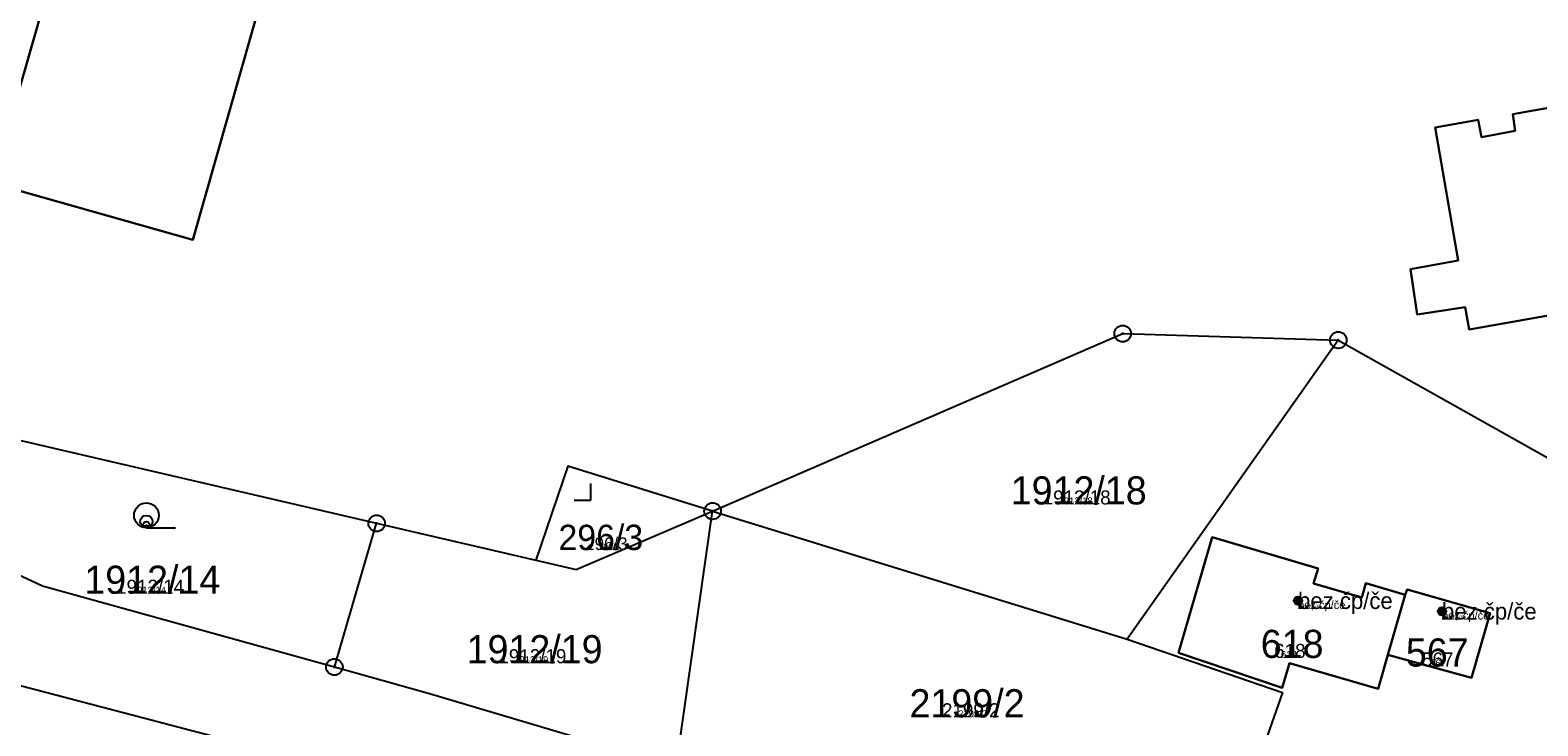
# Model space of a CAD drawing. Extents: x -744652 to -739090, y -980828 to -975855.
# Drawn here: x -742346.1 to -742254.9, y -978565.5 to -978523.4 of the extents above; entities that cross this region are included whole.
import ezdxf

# ---------------------------------------------------------------- set-up
doc = ezdxf.new("R2010")
doc.units = 0
for name, color, linetype in [('KAT_02_hranice parcel', 7, 'Continuous'), ('KAT_03_1000_st čísla parcelní', 7, 'Continuous'), ('KAT_03_1000_čísla parcelní', 7, 'Continuous'), ('KAT_03_1000_čísla popisná', 7, 'Continuous'), ('KAT_03_100_st čísla parcelní', 7, 'Continuous'), ('KAT_03_100_čísla parcelní', 7, 'Continuous'), ('KAT_03_100_čísla popisná', 7, 'Continuous'), ('KAT_03_250_st čísla parcelní', 7, 'Continuous'), ('KAT_03_250_čísla parcelní', 7, 'Continuous'), ('KAT_03_250_čísla popisná', 7, 'Continuous'), ('KAT_03_500_st čísla parcelní', 7, 'Continuous'), ('KAT_03_500_čísla parcelní', 7, 'Continuous'), ('KAT_03_500_čísla popisná', 7, 'Continuous'), ('KAT_05_1000_značky kultur', 7, 'Continuous'), ('KAT_05_100_značky kultur', 7, 'Continuous'), ('KAT_05_250_značky kultur', 7, 'Continuous'), ('KAT_05_500_značky kultur', 7, 'Continuous'), ('KAT_07_1000_značky budov', 7, 'Continuous'), ('KAT_07_100_značky budov', 7, 'Continuous'), ('KAT_07_500_značky budov', 7, 'Continuous'), ('KAT_11_značky bodu BP', 7, 'Continuous'), ('KAT_14_plocha_budovy', 7, 'Continuous')]:
    doc.layers.add(name, color=color, linetype=linetype)

msp = doc.modelspace()

# ---------------------------------------------------------------- linework, layer by layer
at = {"layer": 'KAT_02_hranice parcel'}
for p, q in [((-742266.98, -978542.14), (-742279.73, -978560.22)), ((-742266.98, -978542.14), (-742239.25, -978557.74)), ((-742327.66, -978561.91), (-742325.11, -978553.22)), ((-742325.11, -978553.22), (-742315.48, -978555.45)), ((-742313.05, -978556.01), (-742304.8, -978552.48)), ((-742307, -978567.97), (-742304.8, -978552.48)), ((-742304.8, -978552.48), (-742279.73, -978560.22)), ((-742315.48, -978555.45), (-742313.05, -978556.01)), ((-742262.93, -978557.54), (-742263.98, -978561.18)), ((-742355.44, -978560.72), (-742332.68, -978566.69))]:
    msp.add_line(p, q, dxfattribs=at)
for points in [[(-742321.29, -978483.58), (-742336.22, -978536.07), (-742348.35, -978532.65), (-742333.05, -978479.2)], [(-742256.28, -978529.49), (-742256.42, -978528.48), (-742243.47, -978526.19), (-742243.22, -978527.52), (-742239.22, -978526.8), (-742238.57, -978530.55), (-742238.97, -978530.61), (-742238.72, -978532.25), (-742238.13, -978532.17), (-742237.29, -978537.66), (-742259.07, -978541.51), (-742259.31, -978540.16), (-742262.2, -978540.59), (-742262.61, -978537.85), (-742259.74, -978537.33), (-742261.13, -978529.29), (-742258.52, -978528.83), (-742258.33, -978529.88), (-742256.28, -978529.49)], [(-742304.8, -978552.48), (-742280.01, -978541.75), (-742266.98, -978542.14)], [(-742352.77, -978553.55), (-742351.57, -978547.06), (-742325.11, -978553.22)], [(-742304.8, -978552.48), (-742313.56, -978549.77), (-742315.48, -978555.45)], [(-742327.66, -978561.91), (-742345.31, -978557.03), (-742352.77, -978553.55)], [(-742263.98, -978561.18), (-742264.57, -978563.23), (-742269.93, -978561.68), (-742270.38, -978563.16), (-742276.63, -978561.05), (-742274.6, -978554.05), (-742268.2, -978555.96), (-742268.48, -978556.86), (-742265.55, -978557.7), (-742265.31, -978556.83), (-742262.93, -978557.54)], [(-742262.93, -978557.54), (-742262.82, -978557.23), (-742257.8, -978558.66), (-742258.93, -978562.56), (-742263.98, -978561.18)], [(-742279.73, -978560.22), (-742270.36, -978563.45), (-742274.28, -978574.63)], [(-742307, -978567.97), (-742321.91, -978563.54), (-742327.66, -978561.91)]]:
    msp.add_lwpolyline(points, dxfattribs=at)
at = {"layer": 'KAT_03_1000_čísla popisná'}
for centre in [(-742269.41, -978557.9), (-742269.41, -978557.9), (-742260.71, -978558.54), (-742260.71, -978558.54)]:
    msp.add_circle(centre, 0.25, dxfattribs=at)
at = {"layer": 'KAT_03_100_čísla popisná'}
for centre in [(-742269.41, -978557.9), (-742269.41, -978557.9), (-742260.71, -978558.54), (-742260.71, -978558.54)]:
    msp.add_circle(centre, 0.025, dxfattribs=at)
at = {"layer": 'KAT_03_250_čísla popisná'}
for centre in [(-742269.41, -978557.9), (-742269.41, -978557.9), (-742260.71, -978558.54), (-742260.71, -978558.54)]:
    msp.add_circle(centre, 0.0625, dxfattribs=at)
at = {"layer": 'KAT_03_500_čísla popisná'}
for centre in [(-742269.41, -978557.9), (-742269.41, -978557.9), (-742260.71, -978558.54), (-742260.71, -978558.54)]:
    msp.add_circle(centre, 0.125, dxfattribs=at)
at = {"layer": 'KAT_05_1000_značky kultur'}
for p, q in [((-742312.16, -978551.82), (-742312.16, -978550.82)), ((-742313.161, -978551.82), (-742312.16, -978551.82)), ((-742339.023, -978553.49), (-742337.273, -978553.49))]:
    msp.add_line(p, q, dxfattribs=at)
msp.add_circle((-742339.023, -978552.74), 0.75, dxfattribs=at)
at = {"layer": 'KAT_05_100_značky kultur'}
for p, q in [((-742312.26, -978551.82), (-742312.16, -978551.82)), ((-742312.16, -978551.82), (-742312.16, -978551.72)), ((-742339.029, -978553.49), (-742338.854, -978553.49))]:
    msp.add_line(p, q, dxfattribs=at)
msp.add_circle((-742339.029, -978553.415), 0.075, dxfattribs=at)
at = {"layer": 'KAT_05_250_značky kultur'}
for p, q in [((-742312.41, -978551.82), (-742312.16, -978551.82)), ((-742312.16, -978551.82), (-742312.16, -978551.57)), ((-742339.028, -978553.49), (-742338.591, -978553.49))]:
    msp.add_line(p, q, dxfattribs=at)
msp.add_circle((-742339.028, -978553.302), 0.187, dxfattribs=at)
at = {"layer": 'KAT_05_500_značky kultur'}
for p, q in [((-742312.16, -978551.82), (-742312.16, -978551.32)), ((-742312.66, -978551.82), (-742312.16, -978551.82)), ((-742339.027, -978553.49), (-742338.152, -978553.49))]:
    msp.add_line(p, q, dxfattribs=at)
msp.add_circle((-742339.026, -978553.115), 0.375, dxfattribs=at)
at = {"layer": 'KAT_07_1000_značky budov'}
for centre in [(-742269.417, -978557.899), (-742260.717, -978558.539)]:
    msp.add_circle(centre, 0.175, dxfattribs=at)
at = {"layer": 'KAT_07_100_značky budov'}
for centre in [(-742269.411, -978557.9), (-742260.711, -978558.54)]:
    msp.add_circle(centre, 0.0175, dxfattribs=at)
at = {"layer": 'KAT_07_500_značky budov'}
for centre, radius in [((-742269.413, -978557.9), 0.0875), ((-742269.412, -978557.9), 0.0438), ((-742260.713, -978558.54), 0.0875), ((-742260.712, -978558.54), 0.0438)]:
    msp.add_circle(centre, radius, dxfattribs=at)
at = {"layer": 'KAT_11_značky bodu BP'}
for centre, radius in [((-742280.01, -978541.75), 0.5), ((-742280.01, -978541.75), 0.0303), ((-742266.98, -978542.14), 0.5), ((-742266.98, -978542.14), 0.0303), ((-742304.8, -978552.48), 0.5), ((-742325.11, -978553.22), 0.5), ((-742325.11, -978553.22), 0.0303), ((-742304.8, -978552.48), 0.0303), ((-742327.66, -978561.91), 0.5), ((-742327.66, -978561.91), 0.0303)]:
    msp.add_circle(centre, radius, dxfattribs=at)
at = {"layer": 'KAT_14_plocha_budovy'}
for points in [[(-742333.05, -978479.2), (-742348.35, -978532.65), (-742336.22, -978536.07), (-742321.29, -978483.58)], [(-742262.61, -978537.85), (-742262.2, -978540.59), (-742259.31, -978540.16), (-742259.07, -978541.51), (-742237.29, -978537.66), (-742238.13, -978532.17), (-742238.72, -978532.25), (-742238.97, -978530.61), (-742238.57, -978530.55), (-742239.22, -978526.8), (-742243.22, -978527.52), (-742243.47, -978526.19), (-742256.42, -978528.48), (-742256.28, -978529.49), (-742258.33, -978529.88), (-742258.52, -978528.83), (-742261.13, -978529.29), (-742259.74, -978537.33)], [(-742276.63, -978561.05), (-742270.38, -978563.16), (-742269.93, -978561.68), (-742264.57, -978563.23), (-742263.98, -978561.18), (-742262.93, -978557.54), (-742265.31, -978556.83), (-742265.55, -978557.7), (-742268.48, -978556.86), (-742268.2, -978555.96), (-742274.6, -978554.05)], [(-742257.8, -978558.66), (-742262.82, -978557.23), (-742262.93, -978557.54), (-742263.98, -978561.18), (-742258.93, -978562.56)]]:
    msp.add_lwpolyline(points, close=True, dxfattribs=at)

# ---------------------------------------------------------------- texts
at = {"layer": 'KAT_03_1000_st čísla parcelní'}
for s, height, p in [('296/3', 1.53, (-742314.116, -978554.835)), ('618', 1.7, (-742271.664, -978561.36)), ('567', 1.7, (-742262.894, -978561.88))]:
    msp.add_text(s, height=height, dxfattribs=at).set_placement(p)
at = {"layer": 'KAT_03_1000_čísla parcelní'}
for s, p in [('1912/18', (-742286.778, -978552.08)), ('1912/14', (-742342.778, -978557.48)), ('1912/19', (-742319.668, -978561.68)), ('2199/2', (-742292.895, -978564.95))]:
    msp.add_text(s, height=1.7, dxfattribs=at).set_placement(p)
at = {"layer": 'KAT_03_1000_čísla popisná'}
for s, height, p in [('296/3', 0.0153, (-742310.914, -978554.835)), ('bez čp/če', 1, (-742269.41, -978558.4)), ('bez čp/če', 1, (-742260.71, -978559.04)), ('618', 0.017, (-742270.054, -978561.36)), ('567', 0.017, (-742260.953, -978561.88))]:
    msp.add_text(s, height=height, dxfattribs=at).set_placement(p)
at = {"layer": 'KAT_03_100_st čísla parcelní'}
for s, height, p in [('296/3', 0.153, (-742311.205, -978554.835)), ('618', 0.17, (-742270.2, -978561.36)), ('567', 0.17, (-742261.129, -978561.88))]:
    msp.add_text(s, height=height, dxfattribs=at).set_placement(p)
at = {"layer": 'KAT_03_100_čísla parcelní'}
for s, p in [('1912/18', (-742283.303, -978552.08)), ('1912/14', (-742339.321, -978557.48)), ('1912/19', (-742316.211, -978561.68)), ('2199/2', (-742289.365, -978564.95))]:
    msp.add_text(s, height=0.17, dxfattribs=at).set_placement(p)
at = {"layer": 'KAT_03_100_čísla popisná'}
for s, height, p in [('296/3', 0.00153, (-742310.885, -978554.835)), ('bez čp/če', 0.1, (-742269.41, -978558.4)), ('bez čp/če', 0.1, (-742260.71, -978559.04)), ('618', 0.0017, (-742270.039, -978561.36)), ('567', 0.0017, (-742260.935, -978561.88))]:
    msp.add_text(s, height=height, dxfattribs=at).set_placement(p)
at = {"layer": 'KAT_03_250_st čísla parcelní'}
for s, height, p in [('296/3', 0.3825, (-742311.69, -978554.835)), ('618', 0.425, (-742270.444, -978561.36)), ('567', 0.425, (-742261.423, -978561.88))]:
    msp.add_text(s, height=height, dxfattribs=at).set_placement(p)
at = {"layer": 'KAT_03_250_čísla parcelní'}
for s, p in [('1912/18', (-742283.882, -978552.08)), ('1912/14', (-742339.897, -978557.48)), ('1912/19', (-742316.787, -978561.68)), ('2199/2', (-742289.954, -978564.95))]:
    msp.add_text(s, height=0.425, dxfattribs=at).set_placement(p)
at = {"layer": 'KAT_03_250_čísla popisná'}
for s, height, p in [('296/3', 0.00383, (-742310.89, -978554.835)), ('bez čp/če', 0.25, (-742269.41, -978558.4)), ('bez čp/če', 0.25, (-742260.71, -978559.04)), ('618', 0.00425, (-742270.042, -978561.36)), ('567', 0.00425, (-742260.938, -978561.88))]:
    msp.add_text(s, height=height, dxfattribs=at).set_placement(p)
at = {"layer": 'KAT_03_500_st čísla parcelní'}
for s, height, p in [('296/3', 0.765, (-742312.499, -978554.835)), ('618', 0.85, (-742270.851, -978561.36)), ('567', 0.85, (-742261.914, -978561.88))]:
    msp.add_text(s, height=height, dxfattribs=at).set_placement(p)
at = {"layer": 'KAT_03_500_čísla parcelní'}
for s, p in [('1912/18', (-742284.847, -978552.08)), ('1912/14', (-742340.857, -978557.48)), ('1912/19', (-742317.747, -978561.68)), ('2199/2', (-742290.934, -978564.95))]:
    msp.add_text(s, height=0.85, dxfattribs=at).set_placement(p)
at = {"layer": 'KAT_03_500_čísla popisná'}
for s, height, p in [('296/3', 0.00765, (-742310.898, -978554.835)), ('bez čp/če', 0.5, (-742269.41, -978558.4)), ('bez čp/če', 0.5, (-742260.71, -978559.04)), ('618', 0.0085, (-742270.046, -978561.36)), ('567', 0.0085, (-742260.943, -978561.88))]:
    msp.add_text(s, height=height, dxfattribs=at).set_placement(p)

doc.saveas('drawing.dxf')
